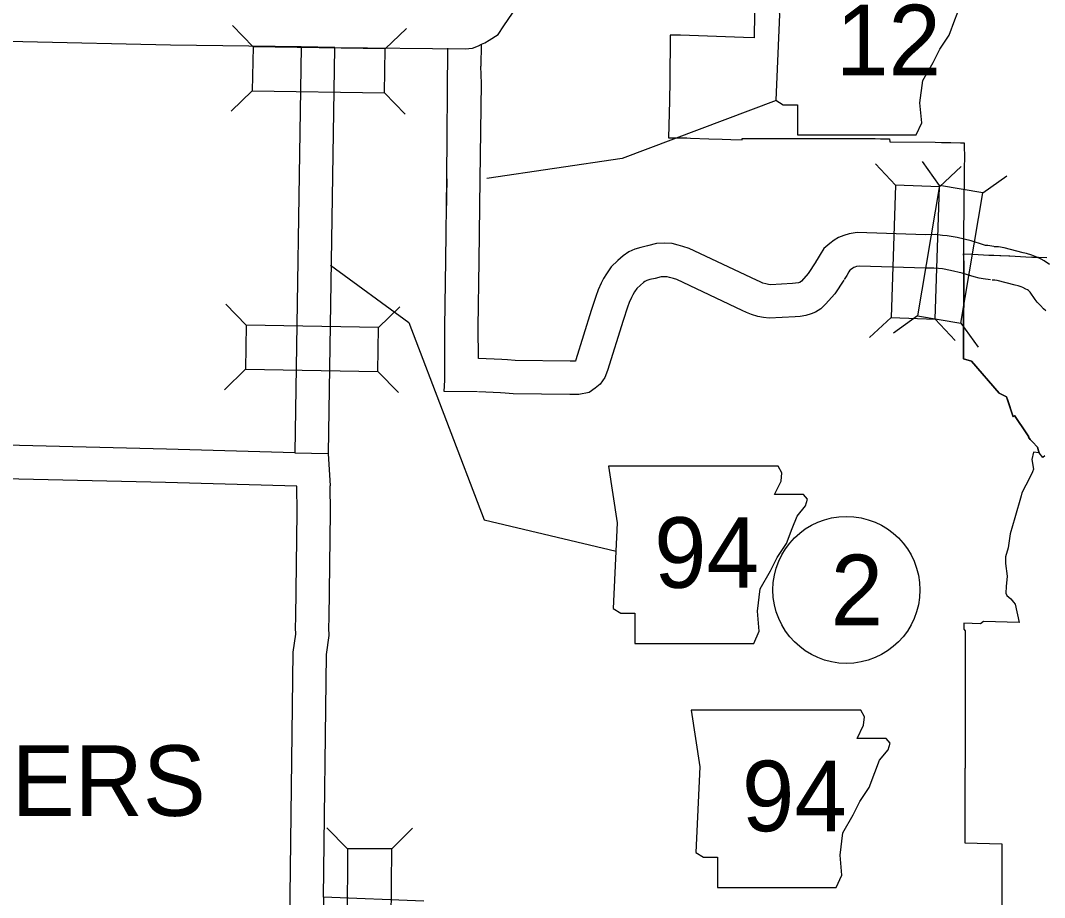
# Model space of a CAD drawing. Extents: x 670147 to 673275, y 705573 to 707613.
# Drawn here: x 670561.9 to 670699.8, y 707300.1 to 707418.2 of the extents above; entities that cross this region are included whole.
import ezdxf

# ---------------------------------------------------------------- set-up
doc = ezdxf.new("R2010")
doc.units = 0
for name, color, linetype in [('10', 7, 'Continuous'), ('15', 7, 'Continuous'), ('20', 7, 'Continuous'), ('21', 7, 'Continuous'), ('22', 7, 'Continuous'), ('27', 7, 'Continuous'), ('6', 7, 'Continuous')]:
    doc.layers.add(name, color=color, linetype=linetype)

msp = doc.modelspace()

# ---------------------------------------------------------------- linework, layer by layer
at = {"layer": '10'}
for points in [[(670599.72, 707414.64), (670582.12, 707414.86), (670562.23, 707415.34), (670542, 707415.79), (670503, 707416.39), (670487.28, 707416.72)], [(670599.72, 707414.64), (670598.85, 707359.96)], [(670604.21, 707414.53), (670603.35, 707359.89)], [(670623.93, 707415), (670623.9, 707412.05)], [(670693.25, 707387.71), (670692.2, 707387.88), (670691.86, 707387.92), (670691.58, 707387.99), (670689.92, 707388.52), (670688.04, 707388.97), (670686.71, 707389.19), (670686.06, 707389.27), (670685.11, 707389.37), (670683.81, 707389.35), (670674.59, 707389.65), (670673.52, 707389.47), (670672.78, 707389.26), (670672.09, 707388.98), (670671.48, 707388.6), (670670.9, 707388.17), (670670.1, 707387.49), (670669.62, 707386.67), (670669.35, 707386.24), (670668.99, 707385.64)], [(670669.03, 707385.71), (670668, 707384.14), (670667.07, 707383.11), (670666.91, 707382.96), (670666.88, 707382.94), (670666.84, 707382.92), (670666.69, 707382.88), (670666.3, 707382.82), (670665.88, 707382.77), (670662.93, 707382.62), (670662.66, 707382.66), (670662.27, 707382.73), (670661.9, 707382.85), (670661.52, 707383), (670661.04, 707383.24), (670651.97, 707387.51), (670651.13, 707387.78), (670650.47, 707387.95), (670649.69, 707388.16), (670648.63, 707388.2), (670647.57, 707388.15), (670646.36, 707387.86), (670645.46, 707387.65), (670644.64, 707387.39), (670643.85, 707387.04), (670643.05, 707386.52), (670642.34, 707385.88), (670641.44, 707385.02), (670640.82, 707384.09), (670640.42, 707383.44), (670640.12, 707382.84), (670639.69, 707381.93), (670639.38, 707381.02), (670638.78, 707379.14), (670636.71, 707372.52), (670636.64, 707372.33), (670635.92, 707372.34), (670628.52, 707372.41), (670627.5, 707372.51), (670626.73, 707372.54), (670623.61, 707372.69)], [(670700.49, 707385.36), (670699.78, 707385.82), (670699.35, 707386.04), (670698.77, 707386.34), (670698.11, 707386.6), (670697.4, 707386.81), (670696.93, 707386.92), (670694.38, 707387.58), (670693.64, 707387.7), (670693.02, 707387.74)], [(670692.55, 707383.27), (670691.56, 707383.42), (670691.03, 707383.49), (670690.36, 707383.66), (670688.71, 707384.18), (670687.14, 707384.55), (670686.07, 707384.74), (670685.55, 707384.8), (670684.91, 707384.87), (670683.78, 707384.84), (670674.9, 707385.14), (670674.51, 707385.07), (670674.26, 707385), (670674.14, 707384.95), (670674, 707384.87), (670673.69, 707384.64), (670673.6, 707384.56), (670673.48, 707384.35), (670673.19, 707383.88), (670672.84, 707383.31)], [(670672.79, 707383.24), (670671.57, 707381.37), (670670.3, 707379.98), (670669.69, 707379.38), (670668.96, 707378.94), (670668.38, 707378.69), (670667.69, 707378.48), (670666.92, 707378.36), (670666.25, 707378.28), (670662.73, 707378.11), (670661.96, 707378.22), (670661.21, 707378.35), (670660.35, 707378.61), (670659.67, 707378.9), (670659.11, 707379.17), (670650.32, 707383.31), (670649.87, 707383.45), (670649.31, 707383.6), (670649.01, 707383.68), (670648.65, 707383.69), (670648.21, 707383.67), (670647.39, 707383.47), (670646.65, 707383.31), (670646.24, 707383.17), (670645.99, 707383.06), (670645.8, 707382.94), (670645.4, 707382.58), (670644.91, 707382.11), (670644.61, 707381.66), (670644.36, 707381.26), (670644.18, 707380.89), (670643.87, 707380.23), (670643.65, 707379.61), (670643.07, 707377.79), (670640.97, 707371.05), (670640.62, 707370.14), (670639.98, 707369.23), (670639.31, 707368.69), (670638.51, 707368.11), (670637.12, 707367.83), (670635.88, 707367.84), (670628.26, 707367.91), (670627.18, 707368.02), (670626.55, 707368.05), (670623.58, 707368.18)], [(670699.99, 707379.12), (670699.68, 707379.39), (670699.27, 707379.8), (670698.85, 707380.25), (670698.57, 707380.65), (670697.88, 707381.6), (670697.74, 707381.76), (670697.67, 707381.83), (670697.54, 707381.91), (670697.28, 707382.04), (670696.9, 707382.24), (670696.66, 707382.34), (670696.26, 707382.45), (670695.86, 707382.55), (670693.43, 707383.17), (670693.14, 707383.22), (670692.78, 707383.24)], [(670616.24, 707299.62), (670602.7, 707300.13), (670602.62, 707295.57)]]:
    msp.add_lwpolyline(points, dxfattribs=at)
at = {"layer": '15'}
for points in [[(670626.22, 707416.32), (670627.01, 707417.49), (670634.6, 707428.62), (670638.66, 707434.32), (670643.07, 707440.33), (670653.1, 707454.13), (670657.12, 707459.78), (670657.83, 707460.96), (670658.76, 707462.46), (670659.67, 707464.14), (670661.72, 707468)], [(670604.22, 707414.58), (670621.79, 707414.39), (670622.76, 707414.48), (670623.58, 707414.81), (670624, 707415.02), (670624.43, 707415.2), (670625.03, 707415.55), (670626.22, 707416.32)], [(670604.22, 707414.58), (670599.72, 707414.64)], [(670619.42, 707414.48), (670619.29, 707396.9)], [(670623.99, 707409.7), (670623.9, 707412.05)], [(670623.57, 707372.69), (670623.55, 707376.88), (670623.67, 707385.85), (670623.82, 707396.83), (670623.99, 707409.7)], [(670618.96, 707368.22), (670619.04, 707369.75), (670619.07, 707372.41), (670619.04, 707376.9), (670619.17, 707385.92), (670619.32, 707396.9)], [(670619.32, 707396.9), (670619.25, 707392.04)], [(670623.46, 707368.19), (670618.96, 707368.22)], [(670598.85, 707360), (670581.55, 707360.48), (670561.76, 707360.95), (670542.18, 707361.28), (670519.91, 707361.67), (670502.15, 707362.08), (670477.19, 707362.69)], [(670598.85, 707360), (670603.35, 707359.87)], [(670603.35, 707359.89), (670603.63, 707355.52)], [(670599.14, 707355.49), (670581.43, 707355.98), (670561.67, 707356.45), (670542.11, 707356.78), (670519.82, 707357.17), (670502.04, 707357.58), (670476.43, 707358.21)], [(670598.17, 707295.82), (670598.22, 707300.3), (670598.65, 707333.13), (670598.97, 707335.57), (670598.93, 707336.41), (670598.99, 707337.87), (670599.15, 707352.01), (670599.13, 707355.49)], [(670602.71, 707300.12), (670603.14, 707332.81), (670603.48, 707335.36), (670603.44, 707336.41), (670603.49, 707337.77), (670603.65, 707352), (670603.63, 707355.52)]]:
    msp.add_lwpolyline(points, dxfattribs=at)
at = {"layer": '20'}
for p, q in [((670593.22, 707414.67), (670590.47, 707417.51)), ((670611.04, 707414.39), (670613.89, 707417.14)), ((670593.13, 707408.73), (670590.29, 707405.98)), ((670610.95, 707408.45), (670613.7, 707405.6)), ((670685.67, 707395.98), (670683.37, 707399.21)), ((670679.74, 707396.01), (670677.04, 707398.9)), ((670685.68, 707395.81), (670688.57, 707398.52)), ((670691.52, 707394.99), (670694.75, 707397.29)), ((670679.74, 707396.01), (670679.15, 707378.2)), ((670685.68, 707395.81), (670679.74, 707396.01)), ((670685.67, 707395.98), (670682.7, 707378.41)), ((670685.09, 707378), (670685.68, 707395.81)), ((670691.52, 707394.99), (670685.67, 707395.98)), ((670688.56, 707377.42), (670691.52, 707394.99)), ((670592.32, 707377.17), (670589.57, 707380.01)), ((670610.14, 707376.88), (670612.98, 707379.64)), ((670682.7, 707378.41), (670679.48, 707376.11)), ((670682.7, 707378.41), (670688.56, 707377.42)), ((670592.32, 707377.17), (670592.23, 707371.23)), ((670610.14, 707376.88), (670592.32, 707377.17)), ((670679.15, 707378.2), (670676.26, 707375.49)), ((670679.15, 707378.2), (670685.09, 707378)), ((670685.09, 707378), (670687.79, 707375.11)), ((670688.56, 707377.42), (670690.86, 707374.19)), ((670610.05, 707370.95), (670610.14, 707376.88)), ((670592.23, 707371.23), (670589.38, 707368.47)), ((670592.23, 707371.23), (670610.05, 707370.95)), ((670610.05, 707370.95), (670612.8, 707368.1)), ((670605.96, 707306.67), (670603.18, 707309.49)), ((670611.9, 707306.64), (670614.72, 707309.43)), ((670605.96, 707306.67), (670605.88, 707293.36)), ((670611.9, 707306.64), (670605.96, 707306.67)), ((670611.8, 707288.82), (670611.9, 707306.64))]:
    msp.add_line(p, q, dxfattribs=at)
msp.add_lwpolyline([(670611.04, 707414.39), (670593.22, 707414.67), (670593.13, 707408.73), (670610.95, 707408.45)], close=True, dxfattribs=at)
at = {"layer": '21'}
for points in [[(670662.99, 707426.64), (670664.13, 707419.03), (670663.62, 707407.48), (670664.64, 707406.85), (670666.54, 707406.85), (670666.54, 707402.79), (670682.53, 707402.79), (670683.29, 707404.43), (670683.03, 707407.1), (670683.41, 707410.14), (670684.81, 707412.56), (670685.7, 707414.33), (670686.97, 707416.24), (670687.73, 707418.27), (670688.36, 707419.91), (670689.5, 707421.31), (670689.76, 707422.2), (670689.25, 707422.83), (670685.32, 707422.83), (670686.21, 707424.61), (670686.33, 707425.75), (670685.81, 707426.63)], [(670641.11, 707358.18), (670642.25, 707350.56), (670641.74, 707339.02), (670642.76, 707338.38), (670644.66, 707338.38), (670644.66, 707334.32), (670660.65, 707334.32), (670661.41, 707335.97), (670661.16, 707338.64), (670661.54, 707341.68), (670662.93, 707344.09), (670663.82, 707345.87), (670665.09, 707347.77), (670665.85, 707349.8), (670666.49, 707351.45), (670667.63, 707352.85), (670667.88, 707353.74), (670667.37, 707354.37), (670663.44, 707354.37), (670664.33, 707356.15), (670664.45, 707357.29), (670663.93, 707358.17)], [(670652.23, 707325.32), (670653.38, 707317.7), (670652.87, 707306.16), (670653.88, 707305.52), (670655.79, 707305.52), (670655.79, 707301.46), (670671.77, 707301.46), (670672.54, 707303.11), (670672.28, 707305.78), (670672.66, 707308.82), (670674.06, 707311.23), (670674.95, 707313.01), (670676.22, 707314.91), (670676.98, 707316.94), (670677.61, 707318.59), (670678.75, 707319.99), (670679.01, 707320.88), (670678.5, 707321.51), (670674.57, 707321.51), (670675.45, 707323.29), (670675.58, 707324.43), (670675.06, 707325.31)]]:
    msp.add_lwpolyline(points, close=True, dxfattribs=at)
msp.add_lwpolyline([(670603.67, 707385.24), (670614.2, 707377.54), (670624.36, 707350.97), (670642.11, 707346.74)], dxfattribs=at)
at = {"layer": '22'}
for p, q in [((670663.69, 707407.43), (670642.92, 707399.61)), ((670642.92, 707399.61), (670624.72, 707396.92))]:
    msp.add_line(p, q, dxfattribs=at)
at = {"layer": '27'}
msp.add_circle((670673.14, 707341.52), 9.9, dxfattribs=at)
at = {"layer": '6'}
for points in [[(670660.84, 707425.78), (670660.72, 707415.86), (670659.26, 707415.9), (670650.81, 707416.23), (670649.42, 707416.24), (670649.35, 707409.98), (670649.3, 707407.54), (670649.3, 707407.39), (670649.19, 707402.42), (670651.66, 707402.38), (670652.16, 707402.35), (670654.6, 707402.28), (670656.39, 707402.22)], [(670656.39, 707402.22), (670657.58, 707402.18), (670659.1, 707402.14), (670659.1, 707402.31), (670664.07, 707402.29), (670668.33, 707402.31), (670669, 707402.31), (670671.01, 707402.31), (670671.2, 707402.31), (670671.88, 707402.31), (670672.87, 707402.3), (670677, 707402.29), (670677.74, 707402.28), (670678.96, 707402.27), (670678.98, 707401.88), (670685.08, 707401.8), (670685.94, 707401.79), (670686.33, 707401.78), (670687.19, 707401.77), (670688.5, 707401.74), (670688.99, 707401.73), (670688.99, 707401.48), (670689.03, 707399.66), (670688.99, 707398.49), (670688.99, 707396.55), (670688.98, 707395.86), (670688.97, 707395.12), (670688.97, 707394.67), (670688.96, 707394.08), (670688.94, 707392.26), (670688.92, 707390.34), (670688.91, 707390.13), (670688.92, 707390.1), (670688.9, 707387.92), (670688.89, 707387.36), (670688.89, 707386.78), (670688.91, 707386.78), (670688.92, 707386.42), (670688.96, 707385.36), (670688.96, 707385.33), (670688.95, 707382.84), (670688.94, 707381.87), (670688.94, 707381.48), (670688.94, 707381.16), (670688.94, 707381.04), (670688.92, 707378.01), (670688.92, 707376.94), (670688.9, 707376.56), (670688.9, 707373.53), (670688.91, 707372.65), (670690, 707372.31), (670693.7, 707368.03), (670694.72, 707367.52), (670694.84, 707367.15), (670695.6, 707364.83), (670695.76, 707365), (670697.42, 707362.53), (670697.7, 707362.12), (670697.68, 707362.11), (670697.9, 707361.79), (670698.22, 707361.45), (670698.89, 707360.73), (670699.02, 707360.26), (670699.11, 707359.96), (670698.34, 707360.08), (670698.13, 707359.07), (670698.32, 707357.77), (670698.2, 707357.4), (670698.05, 707357.11), (670697.31, 707355.64), (670696.77, 707354.58), (670696.68, 707354.21), (670695.83, 707351.22), (670695.5, 707350.13), (670695.19, 707349.07), (670694.93, 707347.17), (670694.56, 707345.99), (670694.55, 707345.06), (670694.78, 707343.38), (670694.64, 707341.97), (670694.6, 707341.08), (670694.73, 707340.75), (670695.29, 707340.33), (670695.63, 707339.86), (670695.88, 707339.6), (670696.39, 707337.15), (670691.61, 707337.26), (670691.21, 707336.97), (670688.94, 707337.02), (670688.94, 707336.22), (670689.11, 707335.99), (670689.11, 707327.42), (670689.11, 707324.17), (670689.11, 707322.41), (670689.11, 707317.52), (670689.1, 707317.52), (670689.09, 707317.36), (670689.08, 707317.36), (670689.08, 707315.15), (670689.08, 707315.1)], [(670699.88, 707359.57), (670699.61, 707359.37), (670699.11, 707359.96), (670699.02, 707360.26), (670698.89, 707360.73), (670698.22, 707361.45), (670697.9, 707361.79), (670697.68, 707362.11), (670697.7, 707362.12), (670697.42, 707362.53), (670695.76, 707365), (670695.6, 707364.83), (670694.72, 707367.52), (670693.7, 707368.03), (670690, 707372.31), (670688.91, 707372.65), (670688.9, 707373.53), (670688.9, 707376.56), (670688.92, 707376.94), (670688.92, 707378.01), (670688.94, 707381.04), (670688.94, 707381.16), (670688.94, 707381.48), (670688.94, 707381.87), (670688.95, 707382.84), (670688.96, 707385.33), (670688.93, 707386.32), (670688.91, 707386.78), (670690.16, 707386.72), (670692.32, 707386.62), (670692.97, 707386.59), (670693.82, 707386.55), (670693.93, 707386.54), (670694.99, 707386.5), (670695.16, 707386.49), (670698, 707386.35), (670698.14, 707386.36), (670698.21, 707386.35), (670698.86, 707386.32), (670699, 707386.31), (670700.12, 707386.3)], [(670689.08, 707315.1), (670689.07, 707307.45), (670694.08, 707307.34), (670694.06, 707297.42)]]:
    msp.add_lwpolyline(points, dxfattribs=at)

# ---------------------------------------------------------------- texts
at = {"layer": '21'}
for s, p in [('12', (670671.73, 707410.82)), ('94', (670647.24, 707341.8)), ('94', (670659.06, 707309.02))]:
    msp.add_text(s, height=9.504, dxfattribs=at).set_placement(p)
at = {"layer": '27'}
msp.add_text('2', height=9.5, dxfattribs=at).set_placement((670671.02, 707336.77))
at = {"layer": '6'}
msp.add_text('ROGERS', height=9.504, dxfattribs=at).set_placement((670531.78, 707311.09))

doc.saveas('drawing.dxf')
